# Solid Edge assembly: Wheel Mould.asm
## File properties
Author: Dan
Template: metric assembly.asm
Last saved by: Dan
Revision: 81
Application: Solid Edge
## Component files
Puller Bar.par
Fixed Half.asm
Moving Half.asm
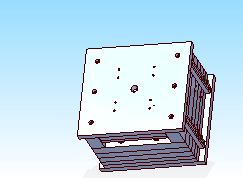
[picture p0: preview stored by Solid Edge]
